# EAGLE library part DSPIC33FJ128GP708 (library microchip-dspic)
dsPIC33 General DSC with CAN and I2S ports
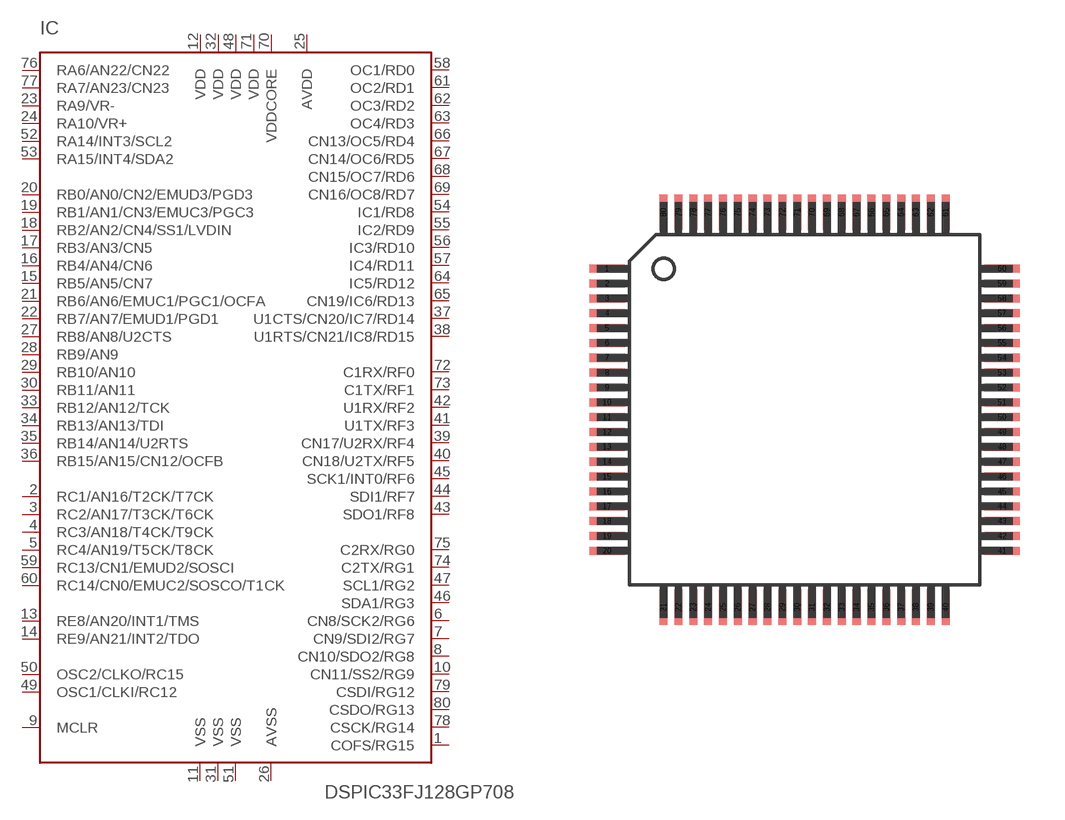
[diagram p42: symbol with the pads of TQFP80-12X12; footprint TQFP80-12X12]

Designator prefix IC

## DSPIC33FJ128GP708/PT  [TQFP80-12X12]
1  COFS/RG15
2  RC1/AN16/T2CK/T7CK
3  RC2/AN17/T3CK/T6CK
4  RC3/AN18/T4CK/T9CK
5  RC4/AN19/T5CK/T8CK
6  CN8/SCK2/RG6
7  CN9/SDI2/RG7
8  CN10/SDO2/RG8
9  MCLR  in
10  CN11/SS2/RG9
11  VSS  pwr
12  VDD  pwr
13  RE8/AN20/INT1/TMS
14  RE9/AN21/INT2/TDO
15  RB5/AN5/CN7
16  RB4/AN4/CN6
17  RB3/AN3/CN5
18  RB2/AN2/CN4/SS1/LVDIN
19  RB1/AN1/CN3/EMUC3/PGC3
20  RB0/AN0/CN2/EMUD3/PGD3
21  RB6/AN6/EMUC1/PGC1/OCFA
22  RB7/AN7/EMUD1/PGD1
23  RA9/VR-
24  RA10/VR+
25  AVDD  pwr
26  AVSS  pwr
27  RB8/AN8/U2CTS
28  RB9/AN9
29  RB10/AN10
30  RB11/AN11
31  VSS  pwr
32  VDD  pwr
33  RB12/AN12/TCK
34  RB13/AN13/TDI
35  RB14/AN14/U2RTS
36  RB15/AN15/CN12/OCFB
37  U1CTS/CN20/IC7/RD14
38  U1RTS/CN21/IC8/RD15
39  CN17/U2RX/RF4
40  CN18/U2TX/RF5
41  U1TX/RF3
42  U1RX/RF2
43  SDO1/RF8
44  SDI1/RF7
45  SCK1/INT0/RF6
46  SDA1/RG3
47  SCL1/RG2
48  VDD  pwr
49  OSC1/CLKI/RC12
50  OSC2/CLKO/RC15
51  VSS  pwr
52  RA14/INT3/SCL2
53  RA15/INT4/SDA2
54  IC1/RD8
55  IC2/RD9
56  IC3/RD10
57  IC4/RD11
58  OC1/RD0
59  RC13/CN1/EMUD2/SOSCI
60  RC14/CN0/EMUC2/SOSCO/T1CK
61  OC2/RD1
62  OC3/RD2
63  OC4/RD3
64  IC5/RD12
65  CN19/IC6/RD13
66  CN13/OC5/RD4
67  CN14/OC6/RD5
68  CN15/OC7/RD6
69  CN16/OC8/RD7
70  VDDCORE  pwr
71  VDD  pwr
72  C1RX/RF0
73  C1TX/RF1
74  C2TX/RG1
75  C2RX/RG0
76  RA6/AN22/CN22
77  RA7/AN23/CN23
78  CSCK/RG14
79  CSDI/RG12
80  CSDO/RG13

## Footprint TQFP80-12X12 (pad centres in mm)
Thin Quad Flat Pack
smd 1.2 x 0.27: 1 -6.65,4.75; 2 -6.65,4.25; 3 -6.65,3.75; 4 -6.65,3.25; 5 -6.65,2.75; 6 -6.65,2.25; 7 -6.65,1.75; 8 -6.65,1.25; 9 -6.65,0.75; 10 -6.65,0.25; 11 -6.65,-0.25; 12 -6.65,-0.75; 13 -6.65,-1.25; 14 -6.65,-1.75; 15 -6.65,-2.25; 16 -6.65,-2.75; 17 -6.65,-3.25; 18 -6.65,-3.75; 19 -6.65,-4.25; 20 -6.65,-4.75; 41 6.65,-4.75; 42 6.65,-4.25; 43 6.65,-3.75; 44 6.65,-3.25; 45 6.65,-2.75; 46 6.65,-2.25; 47 6.65,-1.75; 48 6.65,-1.25; 49 6.65,-0.75; 50 6.65,-0.25; 51 6.65,0.25; 52 6.65,0.75; 53 6.65,1.25; 54 6.65,1.75; 55 6.65,2.25; 56 6.65,2.75; 57 6.65,3.25; 58 6.65,3.75; 59 6.65,4.25; 60 6.65,4.75
smd 0.27 x 1.2: 21 -4.75,-6.65; 22 -4.25,-6.65; 23 -3.75,-6.65; 24 -3.25,-6.65; 25 -2.75,-6.65; 26 -2.25,-6.65; 27 -1.75,-6.65; 28 -1.25,-6.65; 29 -0.75,-6.65; 30 -0.25,-6.65; 31 0.25,-6.65; 32 0.75,-6.65; 33 1.25,-6.65; 34 1.75,-6.65; 35 2.25,-6.65; 36 2.75,-6.65; 37 3.25,-6.65; 38 3.75,-6.65; 39 4.25,-6.65; 40 4.75,-6.65; 61 4.75,6.65; 62 4.25,6.65; 63 3.75,6.65; 64 3.25,6.65; 65 2.75,6.65; 66 2.25,6.65; 67 1.75,6.65; 68 1.25,6.65; 69 0.75,6.65; 70 0.25,6.65; 71 -0.25,6.65; 72 -0.75,6.65; 73 -1.25,6.65; 74 -1.75,6.65; 75 -2.25,6.65; 76 -2.75,6.65; 77 -3.25,6.65; 78 -3.75,6.65; 79 -4.25,6.65; 80 -4.75,6.65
